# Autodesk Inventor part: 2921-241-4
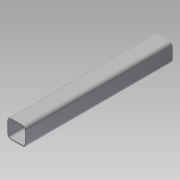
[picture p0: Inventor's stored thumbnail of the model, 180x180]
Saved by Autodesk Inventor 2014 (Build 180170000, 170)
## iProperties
Company: NHTSA/VRTC
Created: 2011-11
Part Number: 2921-241-4
Material: Steel
Document SubType Name: Modeling
Designer: Dave Walker
Density: 7.85 g/cm^3
Project: CHILD SIDE IMPACT SLED
Description: T.S. 2" x 2" x 1/8" x 400.1mm (15.75")
Mass: 1761.38 g
Surface Area: 1424.63 cm^2
Volume: 224.38 cm^3
Stock Number: IMPACTOR FRAME TUBE 4
Appearance: Steel
Author: Dave Walker
Title: Impactor Frame Tube 4
Subject: Child Side Impact Sled
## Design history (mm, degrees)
node "Sketch1"
node "2921-105-41"
node "2921-105-4"
node "Base1"
